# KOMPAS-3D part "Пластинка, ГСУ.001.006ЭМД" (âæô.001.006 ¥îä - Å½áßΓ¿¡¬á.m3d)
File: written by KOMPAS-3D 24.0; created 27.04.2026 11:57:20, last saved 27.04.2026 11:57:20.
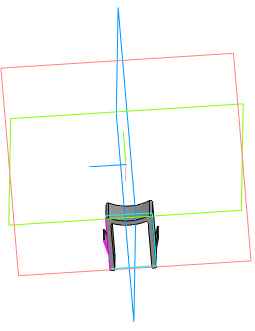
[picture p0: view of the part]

Document properties: Автор: USG_411; Полное имя файла: C:\Users\USG_411.STUD\Desktop\ГМ2704_411-23\Двигатель мясорубки\ГСУ.001.006 ЭМД - Пластинка.m3d

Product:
- Part/product: Пластинка  | designation ГСУ.001.006ЭМД
    Масса: 0.001928

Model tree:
1. Эскиз:1
2. Элемент выдавливания:1
     Расстояние 1 = 7
3. Скругление:1  (with: Ребро.Элемент выдавливания:1)
     Радиус = 0.4
4. Смещенная плоскость:1  (with: Грань.Элемент выдавливания:1)
     Расстояние = 1
5. Эскиз:2  (with: Ребро.Элемент выдавливания:1)
6. Элемент выдавливания:2
     Расстояние 2 = 5
7. Зеркальный массив:1
8. Экземпляр ( 1 )
9. Экземпляр ( 2 )  (with: Элемент выдавливания:2)

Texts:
  ГСУ.001.006
  ГСУ.001.006 ЭМД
